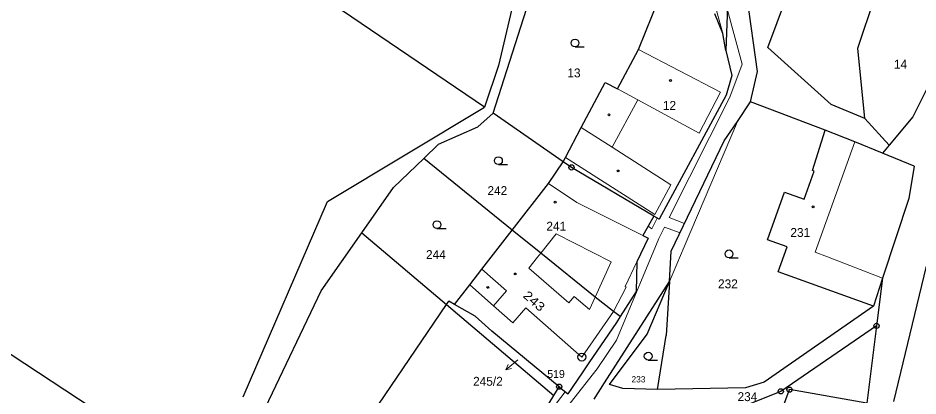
# Model space of a CAD drawing. Extents: x -504006 to -501322, y -1128098 to -1124665.
# Drawn here: x -502830.4 to -502657.9, y -1126896.8 to -1126824.4 of the extents above; entities that cross this region are included whole.
import ezdxf
from ezdxf.enums import TextEntityAlignment as Align

# ---------------------------------------------------------------- set-up
doc = ezdxf.new("R2010")
doc.units = 0
doc.header["$LTSCALE"] = 0.68
for name, color, linetype, lineweight in [('1', 7, 'Continuous', 25), ('13', 7, 'Continuous', 13), ('3', 7, 'Continuous', 25), ('4', 7, 'Continuous', 13), ('5', 7, 'Continuous', 25), ('7', 7, 'Continuous', 13), ('8', 7, 'Continuous', 25)]:
    doc.layers.add(name, color=color, linetype=linetype, lineweight=lineweight)
doc.layers.add('2', color=7, linetype='Continuous')

msp = doc.modelspace()

# ---------------------------------------------------------------- linework, layer by layer
at = {"layer": '1'}
for p, q in [((-502693.34, -1126790.73), (-502694.72, -1126830.65)), ((-502711.5, -1126830.46), (-502705.45, -1126815.51)), ((-502688.66, -1126834.62), (-502691.21, -1126816.43)), ((-502686.7, -1126830.08), (-502681.9, -1126817.21)), ((-502669.47, -1126830.2), (-502665.54, -1126818.43)), ((-502740.97, -1126841.5), (-502773.2, -1126819.62)), ((-502734.84, -1126818.75), (-502738.33, -1126833.52)), ((-502739.32, -1126842.63), (-502732.42, -1126821.09)), ((-502695.3, -1126827.39), (-502696.85, -1126823.62)), ((-502694.72, -1126830.65), (-502695.3, -1126827.39)), ((-502715.51, -1126837.97), (-502711.5, -1126830.46)), ((-502694.72, -1126830.65), (-502693.58, -1126835.44)), ((-502674.59, -1126840.99), (-502686.7, -1126830.08)), ((-502668.15, -1126843.64), (-502669.47, -1126830.2)), ((-502738.33, -1126833.52), (-502740.97, -1126841.5)), ((-502693.58, -1126835.44), (-502694.71, -1126839.18)), ((-502690.02, -1126840.43), (-502688.66, -1126834.62)), ((-502722.44, -1126845.38), (-502717.84, -1126836.73)), ((-502717.84, -1126836.73), (-502715.51, -1126837.97)), ((-502655.79, -1126837.04), (-502658.93, -1126843.34)), ((-502694.71, -1126839.18), (-502707.5, -1126862.93)), ((-502692.54, -1126844.19), (-502690.02, -1126840.43)), ((-502675.72, -1126845.89), (-502690.02, -1126840.43)), ((-502668.15, -1126843.64), (-502674.59, -1126840.99)), ((-502771.06, -1126859.54), (-502740.97, -1126841.5)), ((-502742.29, -1126845.21), (-502739.32, -1126842.63)), ((-502725.9, -1126851.91), (-502739.32, -1126842.63)), ((-502695.05, -1126847.93), (-502692.54, -1126844.19)), ((-502663.45, -1126848.76), (-502668.15, -1126843.64)), ((-502658.93, -1126843.34), (-502663.45, -1126848.76)), ((-502749.77, -1126848.56), (-502742.29, -1126845.21)), ((-502725.47, -1126851.1), (-502722.44, -1126845.38)), ((-502678.15, -1126853.57), (-502675.72, -1126845.89)), ((-502670.01, -1126848.09), (-502675.72, -1126845.89)), ((-502705.22, -1126869.06), (-502695.05, -1126847.93)), ((-502752.61, -1126851.28), (-502749.77, -1126848.56)), ((-502664.74, -1126850.3), (-502670.01, -1126848.09)), ((-502663.45, -1126848.76), (-502664.74, -1126850.3)), ((-502758.42, -1126856.87), (-502752.61, -1126851.28)), ((-502735.67, -1126865), (-502752.61, -1126851.28)), ((-502725.9, -1126851.91), (-502725.47, -1126851.1)), ((-502658.67, -1126852.78), (-502664.74, -1126850.3)), ((-502728.75, -1126856.1), (-502725.9, -1126851.91)), ((-502724.33, -1126853), (-502725.9, -1126851.91)), ((-502708.56, -1126862.35), (-502724.33, -1126853)), ((-502658.67, -1126852.78), (-502659.7, -1126858.98)), ((-502679.73, -1126859.08), (-502677.8, -1126853.69)), ((-502677.8, -1126853.69), (-502678.15, -1126853.57)), ((-502735.67, -1126865), (-502728.75, -1126856.1)), ((-502764.5, -1126865.51), (-502758.42, -1126856.87)), ((-502686.77, -1126866.84), (-502683.54, -1126857.72)), ((-502683.54, -1126857.72), (-502679.73, -1126859.08)), ((-502787.25, -1126896.89), (-502771.06, -1126859.54)), ((-502659.7, -1126858.98), (-502664.71, -1126874.19)), ((-502708.56, -1126862.35), (-502710.66, -1126866.05)), ((-502707.5, -1126862.93), (-502708.56, -1126862.35)), ((-502741.47, -1126872.48), (-502735.67, -1126865)), ((-502730.22, -1126869.42), (-502735.67, -1126865)), ((-502772.27, -1126876.65), (-502764.5, -1126865.51)), ((-502764.5, -1126865.51), (-502748.28, -1126879.25)), ((-502709.64, -1126866.56), (-502711.81, -1126871.08)), ((-502710.66, -1126866.05), (-502709.64, -1126866.56)), ((-502682.98, -1126868.19), (-502686.77, -1126866.84)), ((-502684.7, -1126872.99), (-502682.98, -1126868.19)), ((-502719.8, -1126877.85), (-502730.22, -1126869.42)), ((-502705.56, -1126874.85), (-502705.22, -1126869.06)), ((-502711.81, -1126871.08), (-502711.96, -1126876.75)), ((-502656.38, -1126871.93), (-502662.64, -1126897.84)), ((-502743.8, -1126875.49), (-502741.47, -1126872.48)), ((-502666.48, -1126879.57), (-502684.7, -1126872.99)), ((-502746.72, -1126879.25), (-502743.8, -1126875.49)), ((-502717.98, -1126894.23), (-502705.56, -1126874.85)), ((-502709.85, -1126884.95), (-502705.56, -1126874.85)), ((-502705.56, -1126874.85), (-502706.17, -1126885.19)), ((-502664.71, -1126874.19), (-502666.48, -1126879.57)), ((-502664.71, -1126874.19), (-502665.88, -1126883.34)), ((-502782.92, -1126898.96), (-502772.27, -1126876.65)), ((-502711.96, -1126876.75), (-502714.98, -1126881.56)), ((-502748.28, -1126879.25), (-502747.84, -1126878.61)), ((-502746.72, -1126879.25), (-502747.84, -1126878.61)), ((-502716.27, -1126880.57), (-502719.8, -1126877.85)), ((-502762.47, -1126900.11), (-502748.28, -1126879.25)), ((-502748.28, -1126879.25), (-502727.7, -1126896.67)), ((-502742.75, -1126881.5), (-502746.72, -1126879.25)), ((-502714.98, -1126881.56), (-502716.27, -1126880.57)), ((-502666.48, -1126879.57), (-502687.38, -1126894.13)), ((-502739.61, -1126884.34), (-502742.75, -1126881.5)), ((-502714.98, -1126881.56), (-502715.7, -1126882.72)), ((-502715.7, -1126882.72), (-502721, -1126890.44)), ((-502665.88, -1126883.34), (-502684.22, -1126895.87)), ((-502665.88, -1126883.34), (-502667.76, -1126898.12)), ((-502836.17, -1126885.85), (-502791.71, -1126915.01)), ((-502726.67, -1126894.98), (-502739.61, -1126884.34)), ((-502717.02, -1126894.53), (-502709.85, -1126884.95)), ((-502707.84, -1126895.49), (-502706.17, -1126885.19)), ((-502721, -1126890.44), (-502722.28, -1126892.3)), ((-502722.28, -1126892.3), (-502725.04, -1126896.32)), ((-502719.97, -1126897.34), (-502717.98, -1126894.23)), ((-502714.5, -1126895.32), (-502717.02, -1126894.53)), ((-502687.38, -1126894.13), (-502690.99, -1126895.18)), ((-502727.7, -1126896.67), (-502726.67, -1126894.98)), ((-502726.67, -1126894.98), (-502725.04, -1126896.32)), ((-502707.84, -1126895.49), (-502714.5, -1126895.32)), ((-502690.99, -1126895.18), (-502707.84, -1126895.49)), ((-502684.22, -1126895.87), (-502690.13, -1126898.25)), ((-502685.5, -1126903.59), (-502682.57, -1126895.54)), ((-502667.76, -1126898.12), (-502682.57, -1126895.54)), ((-502745.83, -1126926.36), (-502727.7, -1126896.67))]:
    msp.add_line(p, q, dxfattribs=at)
at = {"layer": '13'}
for points in [[(-502696.9, -1126821.56), (-502695.3, -1126827.39), (-502694.72, -1126830.65), (-502693.98, -1126833.75), (-502693.58, -1126835.44), (-502694.71, -1126839.18), (-502707.5, -1126862.93), (-502707.91, -1126862.71), (-502708.91, -1126864.74), (-502709.64, -1126864.25), (-502710.66, -1126866.05), (-502709.64, -1126866.56), (-502711.81, -1126871.08), (-502711.96, -1126876.75), (-502714.98, -1126881.56), (-502715.7, -1126882.72), (-502717.88, -1126885.89), (-502721, -1126890.44), (-502722.28, -1126892.3), (-502725.04, -1126896.32), (-502725.52, -1126895.93), (-502729.02, -1126900.53)], [(-502727.38, -1126901.69), (-502719.38, -1126891.53), (-502715.73, -1126886.05), (-502707.61, -1126866.62), (-502706.52, -1126864.43), (-502703.52, -1126865.53), (-502702.65, -1126863.72), (-502705.63, -1126862.62), (-502693.97, -1126839.55), (-502691.6, -1126833.24), (-502694.45, -1126822.9)]]:
    msp.add_lwpolyline(points, dxfattribs=at)
at = {"layer": '3'}
for p, q in [((-502723.643, -1126829.94), (-502721.893, -1126829.94)), ((-502738.323, -1126852.47), (-502736.573, -1126852.47)), ((-502750.093, -1126864.72), (-502748.343, -1126864.72)), ((-502694.143, -1126870.31), (-502692.393, -1126870.31)), ((-502709.623, -1126889.89), (-502707.873, -1126889.89))]:
    msp.add_line(p, q, dxfattribs=at)
for centre in [(-502723.6429, -1126829.1898), (-502738.3229, -1126851.7198), (-502750.0929, -1126863.9698), (-502694.1429, -1126869.5598), (-502709.6229, -1126889.1398)]:
    msp.add_circle(centre, 0.75, dxfattribs=at)
at = {"layer": '4'}
for p, q in [((-502711.5, -1126830.46), (-502695.78, -1126838.62)), ((-502711.58, -1126840.09), (-502715.51, -1126837.97)), ((-502695.78, -1126838.62), (-502699.88, -1126846.45)), ((-502711.58, -1126840.09), (-502716.52, -1126849.15)), ((-502699.88, -1126846.45), (-502711.58, -1126840.09)), ((-502702.72, -1126868.18), (-502692.54, -1126844.19)), ((-502722.44, -1126845.38), (-502716.52, -1126849.15)), ((-502716.52, -1126849.15), (-502705.29, -1126856.31)), ((-502670.01, -1126848.09), (-502677.66, -1126869.2)), ((-502708.37, -1126862), (-502725.47, -1126851.1)), ((-502728.75, -1126856.1), (-502723.27, -1126859.75)), ((-502705.29, -1126856.31), (-502708.37, -1126862)), ((-502723.27, -1126859.75), (-502710.66, -1126866.05)), ((-502727.25, -1126865.7), (-502730.22, -1126869.42)), ((-502716.69, -1126871.07), (-502727.25, -1126865.7)), ((-502705.56, -1126874.85), (-502702.72, -1126868.18)), ((-502730.81, -1126870.16), (-502732.49, -1126872.27)), ((-502730.22, -1126869.42), (-502730.81, -1126870.16)), ((-502677.66, -1126869.2), (-502675.3, -1126870.11)), ((-502675.3, -1126870.11), (-502664.71, -1126874.19)), ((-502719.8, -1126877.85), (-502716.69, -1126871.07)), ((-502711.81, -1126871.08), (-502714.06, -1126875.78)), ((-502736.77, -1126876.61), (-502741.47, -1126872.48)), ((-502732.49, -1126872.27), (-502724.83, -1126878.93)), ((-502739.28, -1126879.47), (-502743.8, -1126875.49)), ((-502739.28, -1126879.47), (-502736.77, -1126876.61)), ((-502713.83, -1126875.9), (-502716.27, -1126880.57)), ((-502714.06, -1126875.78), (-502713.83, -1126875.9)), ((-502724.83, -1126878.93), (-502723.83, -1126877.73)), ((-502723.83, -1126877.73), (-502720.88, -1126880.21)), ((-502720.88, -1126880.21), (-502719.8, -1126877.85)), ((-502735.58, -1126882.73), (-502739.28, -1126879.47)), ((-502733.05, -1126879.87), (-502735.58, -1126882.73)), ((-502722.34, -1126889.31), (-502733.05, -1126879.87)), ((-502716.27, -1126880.57), (-502722.34, -1126889.31))]:
    msp.add_line(p, q, dxfattribs=at)
at = {"layer": '5'}
for centre in [(-502705.3568, -1126836.3592), (-502717.1368, -1126842.9292), (-502715.4068, -1126853.6792), (-502727.4568, -1126859.6692), (-502678.0368, -1126860.5592), (-502735.0868, -1126873.3992), (-502740.3468, -1126875.9692)]:
    msp.add_circle(centre, 0.175, dxfattribs=at)
at = {"layer": '7'}
msp.add_line((-502736.912, -1126891.749), (-502735.819, -1126891.507), dxfattribs=at)
msp.add_lwpolyline([(-502734.58, -1126889.86), (-502736.912, -1126891.749), (-502736.449, -1126890.729)], dxfattribs=at)
at = {"layer": '8'}
for centre, radius in [((-502724.33, -1126852.9999), 0.5), ((-502724.33, -1126852.9999), 0.0303), ((-502665.88, -1126883.3399), 0.5), ((-502665.88, -1126883.3399), 0.0303), ((-502722.34, -1126889.3098), 0.75), ((-502722.34, -1126889.3098), 0.03), ((-502726.67, -1126894.9799), 0.5), ((-502726.67, -1126894.9799), 0.0303), ((-502684.22, -1126895.8699), 0.5), ((-502684.22, -1126895.8699), 0.0303), ((-502682.57, -1126895.5399), 0.5), ((-502682.57, -1126895.5399), 0.0303)]:
    msp.add_circle(centre, radius, dxfattribs=at)

# ---------------------------------------------------------------- texts
at = {"layer": '2'}
for s, height, p in [('14', 1.7, (-502661.289, -1126834.105)), ('13', 1.7, (-502723.849, -1126835.765)), ('12', 1.7, (-502705.549, -1126841.985)), ('242', 1.7, (-502738.529, -1126858.295)), ('241', 1.7, (-502727.239, -1126865.105)), ('231', 1.7, (-502680.489, -1126866.305)), ('244', 1.7, (-502750.299, -1126870.545)), ('232', 1.7, (-502694.349, -1126876.135)), ('233', 1.2, (-502711.489, -1126894.16)), ('234', 1.7, (-502690.619, -1126897.735))]:
    msp.add_text(s, height=height, dxfattribs=at).set_placement(p, align=Align.CENTER)
at = {"layer": '2', "width": 1.2}
msp.add_text('243', height=1.7, rotation=319, dxfattribs=at).set_placement((-502732.0341, -1126879.2272), align=Align.CENTER)
at = {"layer": '2'}
msp.add_text('245/2', height=1.7, dxfattribs=at).set_placement((-502737.49, -1126894.795), align=Align.RIGHT)
at = {"layer": '8'}
msp.add_text('519', height=1.5, dxfattribs=at).set_placement((-502725.609, -1126893.295), align=Align.RIGHT)

doc.saveas('drawing.dxf')
